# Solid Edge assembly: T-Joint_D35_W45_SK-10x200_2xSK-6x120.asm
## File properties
Author: fknapp
Template: iso metric assembly.asm
Last saved by: fknapp
Revision: 7
Application: Solid Edge
Username: fknapp
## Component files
T-Joint_D35_W45.par
SK Schraube 6x120_ohne_Gewinde.par
SK Schraube 10x200_ohne_Gewinde_22042020.par
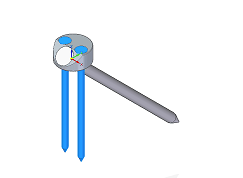
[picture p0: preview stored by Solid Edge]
